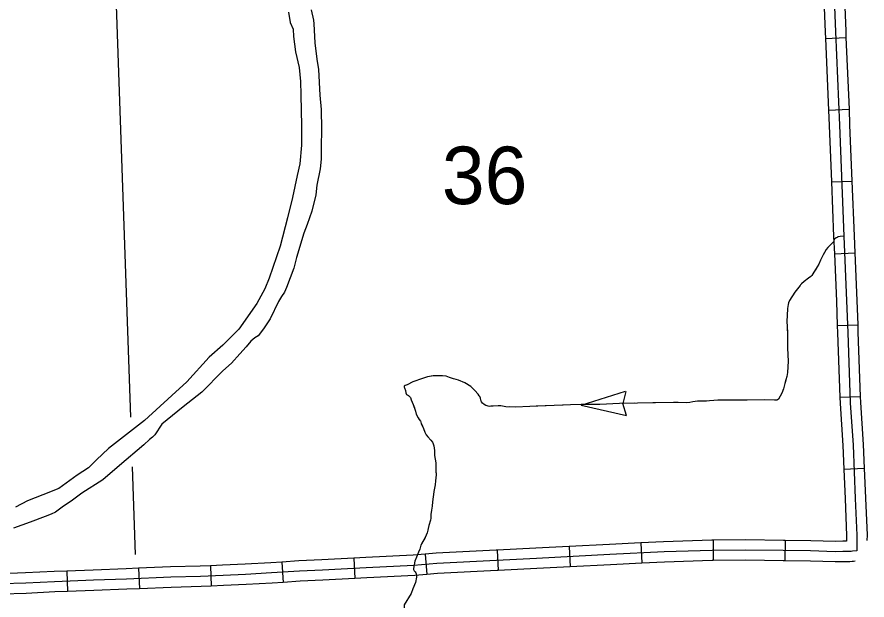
# Model space of a CAD drawing. Extents: x 1720274 to 1751788, y 372074 to 391887.
# Drawn here: x 1740065 to 1741052, y 377198 to 377875 of the extents above; entities that cross this region are included whole.
import ezdxf

# ---------------------------------------------------------------- set-up
doc = ezdxf.new("R2010")
doc.units = 0
for name, color, linetype in [('Level 32', 7, 'Continuous'), ('Level 43', 7, 'Continuous'), ('Level 5', 7, 'Continuous'), ('Level 9', 7, 'Continuous')]:
    doc.layers.add(name, color=color, linetype=linetype)

msp = doc.modelspace()

# ---------------------------------------------------------------- linework, layer by layer
at = {"layer": 'Level 32'}
for p, q in [((1741003.51, 377850.19), (1741027.19, 377851.19)), ((1741007.05, 377766.84), (1741030.73, 377767.85)), ((1741010.36, 377683.52), (1741034.04, 377684.45)), ((1741013.71, 377600.11), (1741037.39, 377601.14)), ((1741017.09, 377516.86), (1741040.78, 377517.69)), ((1741020.09, 377433.48), (1741043.77, 377434.33)), ((1741024.7, 377350.12), (1741048.38, 377351.1)), ((1740788.97, 377264.44), (1740790.15, 377240.77)), ((1740872.84, 377267.6), (1740873, 377243.9)), ((1740956.51, 377267.29), (1740956.17, 377243.59)), ((1740538.64, 377251.28), (1740540.64, 377227.67)), ((1740622.35, 377256.04), (1740623.49, 377232.36)), ((1740705.63, 377260.19), (1740706.86, 377236.52)), ((1740372.27, 377242.18), (1740373.83, 377218.54)), ((1740455.72, 377246.67), (1740456.98, 377223)), ((1740122.56, 377231.7), (1740123.46, 377208.02)), ((1740205.87, 377234.91), (1740206.87, 377211.23)), ((1740289.2, 377237.91), (1740290.27, 377214.23))]:
    msp.add_line(p, q, dxfattribs=at)
for points in [[(1740992.13, 378434.17), (1740992.92, 378419.75), (1740993.43, 378379.95), (1740994.58, 378339.63), (1740996.5, 378304.57), (1741000.59, 378203.59), (1741005.03, 378086.89), (1741010.31, 377974.26), (1741015.04, 377857.92), (1741019.64, 377749.53), (1741024.68, 377620.52), (1741027.95, 377545.4), (1741029.23, 377508.86), (1741032.18, 377426.86), (1741035.41, 377378.07), (1741037.98, 377315.89), (1741039.76, 377273.19), (1741039.7, 377255.28)], [(1741000.1, 377933.56), (1741003.2, 377857.43), (1741003.51, 377850.19)], [(1741023.78, 377934.53), (1741026.88, 377858.42), (1741027.19, 377851.19)], [(1741003.51, 377850.19), (1741007.05, 377766.84)], [(1741027.19, 377851.19), (1741030.73, 377767.85)], [(1741007.05, 377766.84), (1741007.8, 377749.04), (1741010.36, 377683.52)], [(1741030.73, 377767.85), (1741031.48, 377750.01), (1741034.04, 377684.45)], [(1741010.36, 377683.52), (1741012.84, 377620.03), (1741013.71, 377600.11)], [(1741034.04, 377684.45), (1741036.52, 377621.01), (1741037.39, 377601.14)], [(1741013.71, 377600.11), (1741016.11, 377544.94), (1741017.09, 377516.86)], [(1741037.39, 377601.14), (1741039.79, 377545.87), (1741040.78, 377517.69)], [(1741040.78, 377517.69), (1741041.07, 377509.28), (1741043.77, 377434.33)], [(1741017.09, 377516.86), (1741017.39, 377508.44), (1741020.09, 377433.48)], [(1741020.09, 377433.48), (1741020.35, 377426.26), (1741023.57, 377377.44), (1741024.7, 377350.12)], [(1741043.77, 377434.33), (1741044.02, 377427.47), (1741047.24, 377378.71), (1741048.38, 377351.1)], [(1741024.7, 377350.12), (1741026.14, 377315.39), (1741027.91, 377272.97), (1741027.89, 377267.3)], [(1741048.38, 377351.1), (1741049.82, 377316.38), (1741051.61, 377273.42), (1741051.59, 377267.08)], [(1740788.97, 377264.44), (1740752.45, 377262.62), (1740705.63, 377260.19)], [(1740872.84, 377267.6), (1740871.49, 377267.59), (1740815.46, 377265.76), (1740788.97, 377264.44)], [(1740956.51, 377267.29), (1740954.54, 377267.32), (1740911.05, 377267.86), (1740872.84, 377267.6)], [(1741027.89, 377266.27), (1741023.42, 377266.23), (1741014.87, 377266.06), (1740986.35, 377266.86), (1740956.51, 377267.29)], [(1741027.89, 377267.3), (1741027.89, 377266.27)], [(1740954.38, 377255.47), (1740911.02, 377256.01), (1740871.72, 377255.74), (1740815.94, 377253.92), (1740753.05, 377250.79), (1740667.77, 377246.35), (1740621.52, 377244.13), (1740552.27, 377240.55), (1740525.61, 377238.29), (1740470.23, 377235.57), (1740419.28, 377232.86), (1740392.6, 377231.65), (1740360.28, 377229.52), (1740330.02, 377227.8), (1740303.91, 377226.71), (1740277.89, 377225.54), (1740243.38, 377224.63), (1740191.88, 377222.46), (1740153.4, 377221.02), (1740108.14, 377219.3), (1740074.89, 377217.67), (1740046.52, 377216.77)], [(1740538.64, 377251.29), (1740524.82, 377250.11), (1740469.63, 377247.41), (1740455.72, 377246.67)], [(1740622.35, 377256.04), (1740620.93, 377255.97), (1740551.46, 377252.37), (1740538.64, 377251.29)], [(1740705.63, 377260.19), (1740667.18, 377258.19), (1740622.35, 377256.04)], [(1741039.7, 377255.28), (1741034.84, 377254.72), (1741033.38, 377254.6), (1741031.23, 377254.44), (1741023.59, 377254.38), (1741014.82, 377254.2), (1740986.1, 377255.02), (1740954.38, 377255.47)], [(1740372.27, 377242.18), (1740359.56, 377241.34), (1740329.44, 377239.63), (1740303.4, 377238.55), (1740289.2, 377237.91)], [(1740455.72, 377246.67), (1740418.7, 377244.7), (1740391.94, 377243.48), (1740372.27, 377242.18)], [(1740873, 377243.9), (1740871.95, 377243.89), (1740816.43, 377242.08), (1740790.15, 377240.77)], [(1740956.17, 377243.59), (1740954.23, 377243.62), (1740910.99, 377244.16), (1740873, 377243.9)], [(1741037.72, 377243.12), (1741036, 377242.92), (1741034.29, 377242.78), (1741031.71, 377242.59), (1741023.75, 377242.54), (1741014.78, 377242.35), (1740985.84, 377243.17), (1740956.17, 377243.59)], [(1740122.56, 377231.7), (1740107.62, 377231.14), (1740074.41, 377229.51), (1740046.12, 377228.61), (1740039.22, 377228.36)], [(1740205.87, 377234.91), (1740191.41, 377234.3), (1740152.95, 377232.86), (1740122.56, 377231.7)], [(1740289.2, 377237.91), (1740277.47, 377237.38), (1740242.98, 377236.48), (1740205.87, 377234.91)], [(1740623.49, 377232.36), (1740622.11, 377232.3), (1740553.07, 377228.72), (1740540.64, 377227.67)], [(1740706.86, 377236.52), (1740668.36, 377234.52), (1740623.49, 377232.36)], [(1740790.15, 377240.77), (1740753.66, 377238.95), (1740706.86, 377236.52)], [(1740456.98, 377223), (1740419.86, 377221.03), (1740393.26, 377219.82), (1740373.83, 377218.54)], [(1740540.64, 377227.67), (1740526.4, 377226.46), (1740470.84, 377223.74), (1740456.98, 377223)], [(1740290.27, 377214.23), (1740278.31, 377213.69), (1740243.78, 377212.79), (1740206.87, 377211.23)], [(1740373.83, 377218.54), (1740361.01, 377217.69), (1740330.6, 377215.96), (1740304.42, 377214.87), (1740290.27, 377214.23)], [(1740123.46, 377208.02), (1740108.65, 377207.46), (1740075.37, 377205.83), (1740046.93, 377204.92), (1740040.09, 377204.67)], [(1740206.87, 377211.23), (1740192.36, 377210.62), (1740153.85, 377209.17), (1740123.46, 377208.02)]]:
    msp.add_lwpolyline(points, dxfattribs=at)
at = {"layer": 'Level 43'}
for p, q in [((1740719.54, 377424.44), (1740771.34, 377440.48)), ((1740771.57, 377440.37), (1740768.15, 377426.34)), ((1740719.54, 377424.44), (1740772.42, 377412.43)), ((1740772.2, 377412.31), (1740768.15, 377426.15))]:
    msp.add_line(p, q, dxfattribs=at)
for points in [[(1741025.29, 377620.48), (1741020.29, 377620.07), (1741018.63, 377619.86), (1741017.82, 377619.61), (1741016.91, 377619.21), (1741015.76, 377618.45), (1741014.04, 377616.99), (1741012.99, 377615.43), (1741012.53, 377614.02), (1741011.27, 377612.61), (1741006.29, 377607.57), (1741004.37, 377605.1), (1741000.74, 377599), (1740997.74, 377592.77), (1740995.51, 377587.86), (1740990.05, 377578.63), (1740987.59, 377574.86), (1740986.45, 377573.66), (1740983.83, 377571.8), (1740978.7, 377568.09), (1740975.43, 377565.19), (1740974.5, 377564.1), (1740974.12, 377563.45), (1740967.85, 377555.69), (1740961.74, 377545.92), (1740960.59, 377543.19), (1740960.1, 377541.33), (1740959.55, 377539.04), (1740959.39, 377536.58), (1740958.9, 377528.55), (1740958.68, 377521.89), (1740959.23, 377508.62), (1740959.33, 377490.6), (1740960.1, 377475.31), (1740959.12, 377462.09), (1740958.68, 377457.62), (1740957.37, 377453.58), (1740956.39, 377449.43), (1740954.64, 377443.31), (1740952.68, 377438.07), (1740948.75, 377431.19), (1740947.88, 377430.53), (1740946.79, 377430.2), (1740944.17, 377429.99), (1740932.49, 377430.42), (1740912.42, 377430.2), (1740899.21, 377430.31), (1740878.48, 377430.09), (1740863.97, 377429), (1740854.7, 377428.78), (1740849.35, 377428.02), (1740845.97, 377427.58), (1740842.58, 377427.15), (1740832.44, 377427.36), (1740826.98, 377427.58), (1740764.24, 377426.16), (1740741.54, 377425.29), (1740707.28, 377424.85), (1740660.15, 377422.67), (1740643.56, 377421.9), (1740632.43, 377422.56), (1740626.32, 377423.43), (1740623.38, 377423.43), (1740617.7, 377423.11), (1740614.86, 377423), (1740613.12, 377422.89), (1740611.81, 377423), (1740610.61, 377423.43), (1740608.97, 377424.09), (1740607.23, 377425.07), (1740605.26, 377426.82), (1740604.17, 377428.24), (1740603.41, 377429.33), (1740603.19, 377430.09), (1740602.64, 377432.39), (1740601.99, 377434.46), (1740601.44, 377435.12), (1740600.13, 377437.08), (1740596.42, 377441.34), (1740591.62, 377445.82), (1740584.75, 377450.08), (1740577.44, 377453.36), (1740574.38, 377454.23), (1740571.66, 377455), (1740566.96, 377456.63), (1740563.04, 377457.84), (1740558.67, 377458.38), (1740553.98, 377458.49), (1740547.98, 377458.27), (1740541.32, 377457.29), (1740535.54, 377455.43), (1740524.19, 377451.61), (1740517.54, 377448.12), (1740515.24, 377447.02), (1740514.26, 377446.26), (1740514.26, 377445.82), (1740514.26, 377445.17), (1740514.48, 377444.29)], [(1741013.04, 377615.51), (1741012.99, 377615.43), (1741012.53, 377614.02), (1741011.27, 377612.61), (1741006.29, 377607.57), (1741004.37, 377605.1), (1741002.51, 377601.97)], [(1740992.92, 377583.47), (1740990.05, 377578.63), (1740987.59, 377574.86), (1740986.45, 377573.66), (1740983.83, 377571.8), (1740978.7, 377568.09), (1740975.43, 377565.19), (1740974.5, 377564.1), (1740974.12, 377563.45), (1740967.85, 377555.69), (1740961.74, 377545.92), (1740960.59, 377543.19), (1740960.1, 377541.33), (1740959.55, 377539.04), (1740959.39, 377536.58), (1740959.18, 377533.11)], [(1740959.08, 377512.28), (1740959.23, 377508.62), (1740959.33, 377490.6), (1740960.1, 377475.31), (1740959.12, 377462.09), (1740958.68, 377457.62), (1740957.37, 377453.58), (1740956.55, 377450.09)], [(1740546.02, 377457.98), (1740541.32, 377457.29), (1740535.54, 377455.43), (1740524.19, 377451.61), (1740517.54, 377448.12), (1740515.24, 377447.02), (1740514.26, 377446.26), (1740514.26, 377445.82), (1740514.26, 377445.17), (1740514.48, 377444.29), (1740515.61, 377441.26), (1740515.99, 377438.75), (1740516.37, 377437.61), (1740516.97, 377436.84), (1740517.9, 377436.14), (1740519.26, 377435.54), (1740520.02, 377434.77), (1740521.38, 377433.25), (1740522.47, 377430.52), (1740524.65, 377425.24), (1740526, 377421.37)], [(1740615.41, 377423.02), (1740614.86, 377423), (1740613.12, 377422.89), (1740611.81, 377423), (1740610.61, 377423.43), (1740608.97, 377424.09), (1740607.23, 377425.07), (1740605.26, 377426.82), (1740604.17, 377428.24), (1740603.41, 377429.33), (1740603.19, 377430.09), (1740602.64, 377432.39), (1740601.99, 377434.46), (1740601.44, 377435.12), (1740600.13, 377437.08), (1740596.42, 377441.34), (1740591.62, 377445.82), (1740584.75, 377450.08), (1740577.44, 377453.36), (1740574.38, 377454.23), (1740571.66, 377455), (1740566.96, 377456.63), (1740566.65, 377456.73)], [(1740514.48, 377444.29), (1740515.61, 377441.26), (1740515.99, 377438.75), (1740516.37, 377437.61), (1740516.97, 377436.84), (1740517.9, 377436.14), (1740519.26, 377435.54), (1740520.02, 377434.77), (1740521.38, 377433.25), (1740522.47, 377430.52), (1740524.65, 377425.24), (1740527.37, 377417.44), (1740528.13, 377413.95), (1740530.64, 377409.48), (1740531.62, 377407.52), (1740533.14, 377405.78), (1740533.69, 377404.8), (1740534.12, 377402.84), (1740536.52, 377397.17), (1740538.15, 377392.81), (1740539.9, 377389.86), (1740541.86, 377387.47), (1740545.23, 377383.87), (1740547.08, 377381.36), (1740547.95, 377379.4), (1740548.5, 377377), (1740549.26, 377371.55), (1740549.37, 377365.88), (1740551.11, 377357.38), (1740550.9, 377353.02), (1740550.79, 377347.79), (1740551.33, 377343.43), (1740550.46, 377336.45), (1740550.13, 377331.76), (1740548.61, 377324.13), (1740548.06, 377317.81), (1740546.97, 377312.14), (1740546.54, 377307.13), (1740545.89, 377302.22), (1740545.23, 377297.32), (1740545.23, 377293.18), (1740544.69, 377290.78), (1740542.84, 377284.45), (1740542.07, 377281.29), (1740541.75, 377279), (1740540.88, 377276.17), (1740538.48, 377270.83), (1740533.69, 377261.89), (1740532.27, 377257.31), (1740530.75, 377253.61), (1740528.46, 377247.94), (1740526.5, 377243.25), (1740524.98, 377234.75), (1740525.19, 377233.44), (1740525.63, 377232.13), (1740526.94, 377230.71), (1740527.59, 377229.62), (1740528.24, 377228.32), (1740528.57, 377227.12), (1740528.46, 377224.5), (1740527.48, 377218.29), (1740524.43, 377211.2), (1740522.25, 377205.64), (1740514.3, 377192.45)], [(1740865.36, 377429.11), (1740863.97, 377429), (1740854.7, 377428.78), (1740849.35, 377428.02), (1740845.97, 377427.58), (1740842.58, 377427.15), (1740832.44, 377427.36), (1740826.98, 377427.58), (1740802.92, 377427.04)], [(1740948.52, 377431.01), (1740947.88, 377430.53), (1740946.79, 377430.2), (1740944.17, 377429.99), (1740932.49, 377430.42), (1740912.42, 377430.2), (1740899.21, 377430.31), (1740886.18, 377430.18)], [(1740667.43, 377423.01), (1740660.15, 377422.67), (1740643.56, 377421.9), (1740636.19, 377422.34)], [(1740698.68, 377424.45), (1740667.43, 377423.01)], [(1740782.07, 377426.57), (1740764.24, 377426.16), (1740741.54, 377425.29), (1740719.53, 377425.01)], [(1740534.27, 377402.5), (1740536.52, 377397.17), (1740538.15, 377392.81), (1740539.9, 377389.86), (1740541.86, 377387.47), (1740545.23, 377383.87), (1740547.08, 377381.36), (1740547.95, 377379.4), (1740548.5, 377377), (1740549.26, 377371.55), (1740549.37, 377365.88), (1740551.11, 377357.38), (1740550.9, 377353.02), (1740550.79, 377347.79), (1740551.22, 377344.32)], [(1740548.57, 377323.69), (1740548.06, 377317.81), (1740546.97, 377312.14), (1740546.54, 377307.13), (1740545.89, 377302.22), (1740545.23, 377297.32), (1740545.23, 377293.18), (1740544.69, 377290.78), (1740542.84, 377284.45), (1740542.07, 377281.29), (1740541.75, 377279), (1740540.88, 377276.17), (1740538.48, 377270.83), (1740534.51, 377263.43)], [(1740528.55, 377226.64), (1740528.46, 377224.5), (1740527.48, 377218.29), (1740524.43, 377211.2), (1740522.25, 377205.64), (1740514.3, 377192.45), (1740514.19, 377190.49), (1740513.87, 377186.13), (1740513.87, 377186.02)]]:
    msp.add_lwpolyline(points, dxfattribs=at)
at = {"layer": 'Level 5'}
for points in [[(1740173.77, 378066.75), (1740196.29, 377410.31)], [(1740198.27, 377352.71), (1740201.76, 377250.96)]]:
    msp.add_lwpolyline(points, dxfattribs=at)
at = {"layer": 'Level 9'}
for points in [[(1740406.31, 377883.52), (1740408.98, 377871.4), (1740409.22, 377867.28), (1740410.31, 377845.23), (1740412.85, 377826.09), (1740414.66, 377813.97), (1740416.12, 377784.29), (1740417.69, 377767.57), (1740418.05, 377744.91), (1740417.69, 377723.95), (1740417.93, 377709.9), (1740416.48, 377698.87), (1740412.97, 377679.97), (1740411.76, 377668.58), (1740406.92, 377649.68), (1740401.59, 377633.93), (1740397.6, 377623.88), (1740389.37, 377595.65), (1740385.98, 377583.53), (1740377.63, 377561.12), (1740375.21, 377555.66), (1740371.94, 377550.33), (1740368.43, 377544.64), (1740358.5, 377524.65), (1740350.88, 377513.02), (1740344.58, 377504.78), (1740340.83, 377502.48), (1740335.99, 377498.6), (1740330.91, 377491.94), (1740323.4, 377484.06), (1740313.72, 377473.16), (1740303.67, 377464.31), (1740279.1, 377439.47), (1740257.43, 377422.51), (1740232.98, 377402.16), (1740230.32, 377398.89), (1740226.81, 377393.31), (1740224.75, 377389.92), (1740222.09, 377387.25), (1740218.58, 377384.47), (1740211.92, 377378.41), (1740183.84, 377354.42), (1740164.23, 377337.46), (1740140.03, 377322.07), (1740129.13, 377313.95), (1740117.15, 377305.84), (1740109.4, 377300.14), (1740104.44, 377297.6), (1740097.42, 377294.93), (1740079.87, 377288.39), (1740060.63, 377281.48)], [(1740379.7, 377880.65), (1740381.77, 377868.54), (1740385.27, 377860.74), (1740385.59, 377852.29), (1740387.98, 377834.44), (1740392.44, 377816.6), (1740393.87, 377800.02), (1740394.35, 377784.73), (1740394.99, 377748.72), (1740394.99, 377726.41), (1740393.23, 377704.58), (1740389.89, 377691.19), (1740384.64, 377665.38), (1740378.91, 377641.95), (1740370.15, 377608.97), (1740357.58, 377571.84), (1740352.48, 377559.25), (1740343.09, 377542.52), (1740322.39, 377512.4), (1740303.77, 377493.92), (1740287.85, 377480.22), (1740261.74, 377451.53), (1740244.39, 377435.44), (1740212.71, 377406.6), (1740170.69, 377373.93), (1740157, 377360.86), (1740147.6, 377351.62), (1740134.55, 377343.02), (1740113.06, 377327.56), (1740094.75, 377320.39), (1740076.92, 377313.06), (1740063.07, 377305.73)]]:
    msp.add_lwpolyline(points, dxfattribs=at)

# ---------------------------------------------------------------- texts
at = {"layer": 'Level 5'}
msp.add_text('36', height=66.739, dxfattribs=at).set_placement((1740557.96, 377657.79))

doc.saveas('drawing.dxf')
